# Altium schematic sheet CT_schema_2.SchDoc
size 313 x 185 mm
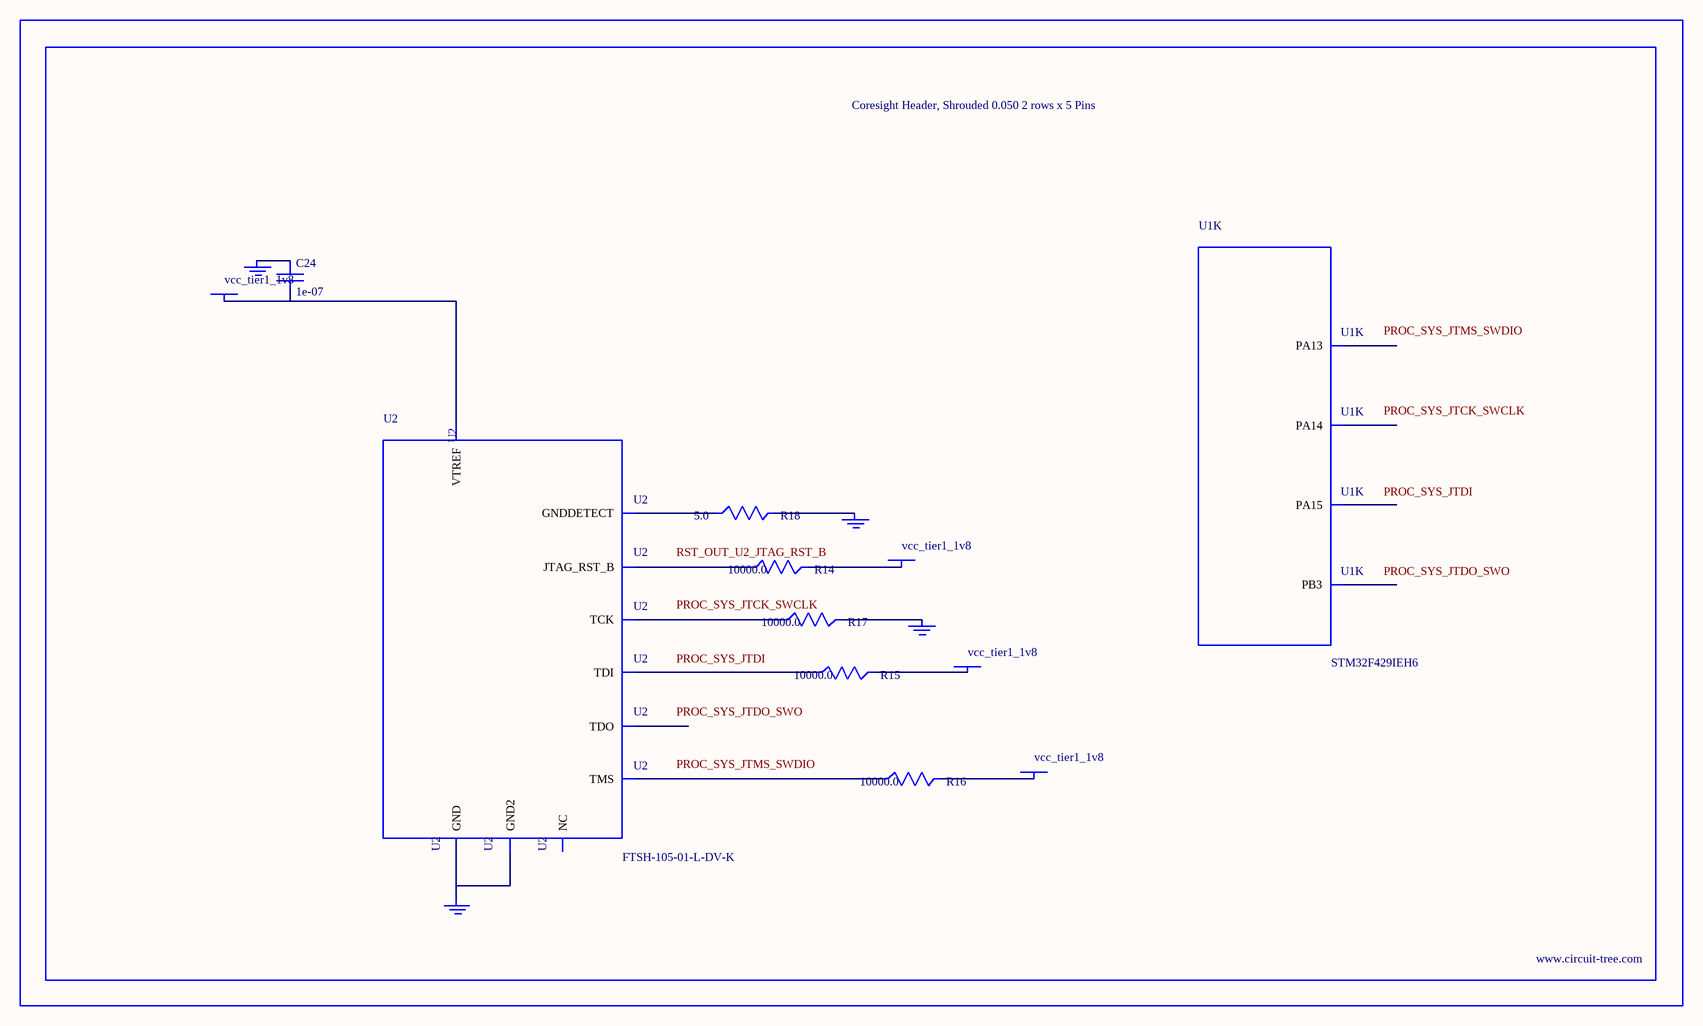
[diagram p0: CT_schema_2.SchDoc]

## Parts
BORDER1  (no value)
C24  1e-07  [C0402]
GND_INSTANCE_1_0  (no value)
GND_INSTANCE_1_1  (no value)
GND_INSTANCE_1_2  (no value)
GND_INSTANCE_1_3  (no value)
POWER_INSTANCE_1_0  vcc_tier1_1v8
POWER_INSTANCE_1_1  vcc_tier1_1v8
POWER_INSTANCE_1_2  vcc_tier1_1v8
POWER_INSTANCE_1_3  vcc_tier1_1v8
R14  10000.0  [R0603]
R15  10000.0  [R0603]
R16  10000.0  [R0603]
R17  10000.0  [R0603]
R18  5.0  [R0603]
U1  STM32F429IEH6  [UFBGA176_25]  (part K of 15)
U2  FTSH-105-01-L-DV-K  [SAMTEC_FTSH-105-01-L-DV-K]

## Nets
NetC24_1: C24.1 GND_INSTANCE_1_0.0(GND)
NetC24_2: C24.2 POWER_INSTANCE_1_0.0(PWR) U2.1(VTREF)
NetGND_INSTANCE_1_1_0: GND_INSTANCE_1_1.0(GND) R17.2
NetGND_INSTANCE_1_2_0: GND_INSTANCE_1_2.0(GND) R18.2
NetGND_INSTANCE_1_3_0: GND_INSTANCE_1_3.0(GND) U2.3(GND) U2.5(GND2)
NetPOWER_INSTANCE_1_1_0: POWER_INSTANCE_1_1.0(PWR) R16.2
NetPOWER_INSTANCE_1_2_0: POWER_INSTANCE_1_2.0(PWR) R15.2
NetPOWER_INSTANCE_1_3_0: POWER_INSTANCE_1_3.0(PWR) R14.2
NetR14_1: R14.1 U2.10(JTAG_RST_B)
NetR15_1: R15.1 U2.8(TDI)
NetR16_1: R16.1 U2.2(TMS)
NetR17_1: R17.1 U2.4(TCK)
NetR18_1: R18.1 U2.9(GNDDETECT)

Not connected (* = marked no-connect by the designer): U1 A10(PB3) A13(PA15) A14(PA14) A15(PA13); U2 6(TDO) 7(NC)

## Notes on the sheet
- Labels drawn without touching a wire or pin: PROC_SYS_JTCK_SWCLK, PROC_SYS_JTDI, PROC_SYS_JTDO_SWO, PROC_SYS_JTMS_SWDIO, RST_OUT_U2_JTAG_RST_B

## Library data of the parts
BORDER1 = BORDER_PAGE1
C24 = C0402C104K3RACTU
GND_INSTANCE_1_0-GND_INSTANCE_1_3 = GND
POWER_INSTANCE_1_0-POWER_INSTANCE_1_3 = PWR
R14-R17 = RC0603JR-0710KL
R18 = ERJ-3GEYJ5R1V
